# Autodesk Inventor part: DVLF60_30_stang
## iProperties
Created: 2010-03
Part Number: DVLF60_30_stang
Document SubType Name: Modeling
Designer: TB
Mass: 247.082 g
Surface Area: 317.171 cm^2
Volume: 247.082 cm^3
Density: 1 g/cm^3
Author: TB
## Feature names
1. Revolution1
2. Fillet1
3. Revolution2
